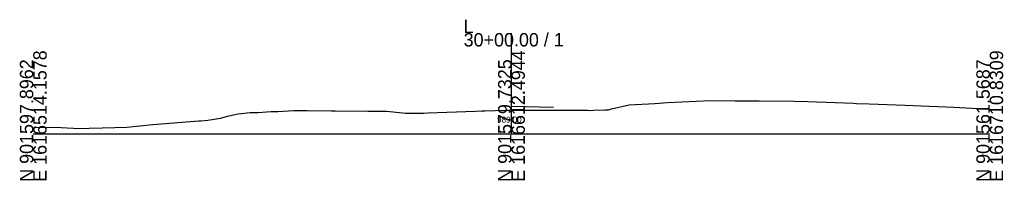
# Model space of a CAD drawing. Extents: x 1009 to 7438, y -1586 to 7964.
# Drawn here: x 2032.1 to 2237.7, y 7914 to 7947.6 of the extents above; entities that cross this region are included whole.
import ezdxf

# ---------------------------------------------------------------- set-up
doc = ezdxf.new("R2010")
doc.units = 0
for name, color, linetype in [('Default', 7, 'Continuous'), ('Exist Cross Section Cell', 7, 'Continuous'), ('Exist XS Center Line Elevation Label', 7, 'Continuous'), ('Exist XS Ground Line', 7, 'Continuous')]:
    doc.layers.add(name, color=color, linetype=linetype)

msp = doc.modelspace()

# ---------------------------------------------------------------- linework, layer by layer
at = {"layer": 'Default'}
msp.add_line((2134.89, 7929.53), (2143.64, 7929.36), dxfattribs=at)
at = {"layer": 'Exist Cross Section Cell'}
for p, q in [((2134.89, 7923.73), (2134.89, 7944.82)), ((2034.89, 7923.73), (2134.89, 7923.73)), ((2134.89, 7923.73), (2234.89, 7923.73))]:
    msp.add_line(p, q, dxfattribs=at)
at = {"layer": 'Exist XS Ground Line'}
for p, q in [((2155.83, 7928.96), (2159.51, 7929.82)), ((2159.51, 7929.82), (2164.88, 7930.13)), ((2164.88, 7930.13), (2167.5, 7930.32)), ((2167.5, 7930.32), (2176.5, 7930.76)), ((2176.5, 7930.76), (2181.68, 7930.67)), ((2181.68, 7930.67), (2186.67, 7930.65)), ((2186.67, 7930.65), (2193.93, 7930.56)), ((2193.93, 7930.56), (2196.84, 7930.53)), ((2196.84, 7930.53), (2206.4, 7930.14)), ((2206.4, 7930.14), (2207.01, 7930.11)), ((2207.01, 7930.11), (2209.71, 7930.01)), ((2209.71, 7930.01), (2217.18, 7929.72)), ((2217.18, 7929.72), (2218.87, 7929.67)), ((2218.87, 7929.67), (2227.35, 7929.35)), ((2227.35, 7929.35), (2234.89, 7928.94)), ((2071.37, 7926.59), (2074.01, 7927.06)), ((2074.01, 7927.06), (2075.82, 7927.51)), ((2075.82, 7927.51), (2076.12, 7927.61)), ((2076.12, 7927.61), (2077.76, 7927.97)), ((2077.76, 7927.97), (2078.45, 7928)), ((2078.45, 7928), (2079.62, 7928.17)), ((2079.62, 7928.17), (2080.25, 7928.2)), ((2080.25, 7928.2), (2081.93, 7928.24)), ((2081.93, 7928.24), (2083.67, 7928.35)), ((2083.67, 7928.35), (2084.61, 7928.4)), ((2084.61, 7928.4), (2086.01, 7928.44)), ((2086.01, 7928.44), (2088.29, 7928.59)), ((2088.29, 7928.59), (2089.42, 7928.61)), ((2089.42, 7928.61), (2090.78, 7928.66)), ((2090.78, 7928.66), (2092.16, 7928.65)), ((2092.16, 7928.65), (2097.22, 7928.57)), ((2097.22, 7928.57), (2098.04, 7928.57)), ((2098.04, 7928.57), (2104.88, 7928.53)), ((2104.88, 7928.53), (2108.82, 7928.53)), ((2108.82, 7928.53), (2112.74, 7928.11)), ((2112.74, 7928.11), (2113.04, 7928.08)), ((2113.04, 7928.08), (2115.33, 7928.09)), ((2115.33, 7928.09), (2116.05, 7928.09)), ((2116.05, 7928.09), (2116.47, 7928.07)), ((2116.47, 7928.07), (2117.4, 7928.15)), ((2117.4, 7928.15), (2127.33, 7928.5)), ((2127.33, 7928.5), (2128.69, 7928.55)), ((2128.69, 7928.55), (2129.29, 7928.58)), ((2129.29, 7928.58), (2133.65, 7928.73)), ((2133.65, 7928.73), (2134.89, 7928.73)), ((2134.89, 7928.73), (2138.13, 7928.73)), ((2138.13, 7928.73), (2138.76, 7928.73)), ((2138.76, 7928.73), (2141.83, 7928.73)), ((2141.83, 7928.73), (2149.99, 7928.69)), ((2149.99, 7928.69), (2150.79, 7928.67)), ((2150.79, 7928.67), (2151.16, 7928.66)), ((2151.16, 7928.66), (2152.02, 7928.69)), ((2152.02, 7928.69), (2154.42, 7928.77)), ((2154.42, 7928.77), (2155.17, 7928.77)), ((2155.17, 7928.77), (2155.83, 7928.96)), ((2034.89, 7925.04), (2035.25, 7925.05)), ((2035.25, 7925.05), (2039.4, 7925.15)), ((2039.4, 7925.15), (2043.34, 7924.93)), ((2043.34, 7924.93), (2043.93, 7924.89)), ((2043.93, 7924.89), (2051.94, 7925.1)), ((2051.94, 7925.1), (2054.47, 7925.18)), ((2054.47, 7925.18), (2059.9, 7925.68)), ((2059.9, 7925.68), (2069.54, 7926.47)), ((2069.54, 7926.47), (2069.92, 7926.5)), ((2069.92, 7926.5), (2071.37, 7926.59))]:
    msp.add_line(p, q, dxfattribs=at)

# ---------------------------------------------------------------- texts
at = {"layer": 'Exist Cross Section Cell'}
for s, p in [('L', (2124.89, 7944.82)), ('30+00.00 / 1', (2124.89, 7942.02))]:
    msp.add_text(s, height=2.8, dxfattribs=at).set_placement(p)
for s, p in [('E 1616514.1578', (2037.69, 7913.73)), ('E 1616612.4944', (2137.69, 7913.73)), ('E 1616710.8309', (2237.69, 7913.73)), ('N 901597.8962', (2034.89, 7913.73)), ('N 901579.7325', (2134.89, 7913.73)), ('N 901561.5687', (2234.89, 7913.73))]:
    msp.add_text(s, height=2.8, rotation=90, dxfattribs=at).set_placement(p)
at = {"layer": 'Exist XS Center Line Elevation Label'}
msp.add_text('989.00', height=1.25, dxfattribs=at).set_placement((2131.89, 7926.1))

doc.saveas('drawing.dxf')
